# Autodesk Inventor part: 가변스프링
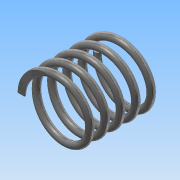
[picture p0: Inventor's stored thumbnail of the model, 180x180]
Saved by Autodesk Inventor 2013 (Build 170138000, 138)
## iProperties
Created: 2017-12
Part Number: 가변스프링
Material: 스테인리스강
Document SubType Name: Modeling
Designer: Administrator
Density: 8.08 g/cm^3
Mass: 7.07029 g
Surface Area: 17.7388 cm^2
Volume: 0.875036 cm^3
Author: Administrator
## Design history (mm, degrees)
sketch "스케치1"
  geometry: L1 (0, 0)-(-9, 0); L2 (-9, 0)-(-9, 22.647); L3 (-9, 22.647)-(0, 22.647); L4 (0, 22.647)-(0, 0); C1 r 1 at (-9, 0)
  constraints: 8 end point, 2 parallel, 1 centre point, 1 coincident, 1 horizontal, 1 perpendicular
  dimensions: "d1" = 22.64683 distance of L1.end L2.end (derived); "d2" = 2 diameter of C1; "d13" = 18 diameter of L2 L4
feature "코일1" sketch "스케치1" pitch "d3" = 10; turns "d5" = 5; dims "d4" = 22.64683 (= d1), "d6" = 0, angle "d7" = 90 deg, angle "d8" = 90 deg, "d9" = 0, "d10" = 0
sketch "스케치2"
  geometry: L1 (0, -26.74)-(22.647, -26.74); L2 (22.647, -26.74)-(22.647, 27.085); L3 (22.647, 27.085)-(0, 27.085); L4 (0, 27.085)-(0, -26.74); 4 further points
  constraints: 8 end point, 2 midpoint, 2 parallel, 2 vertical alignment, 1 horizontal, 1 perpendicular
extrude "돌출1" sketch "스케치2" stored distance "d11" = 0; taper "d12" = 0 deg
node "솔리드1"
